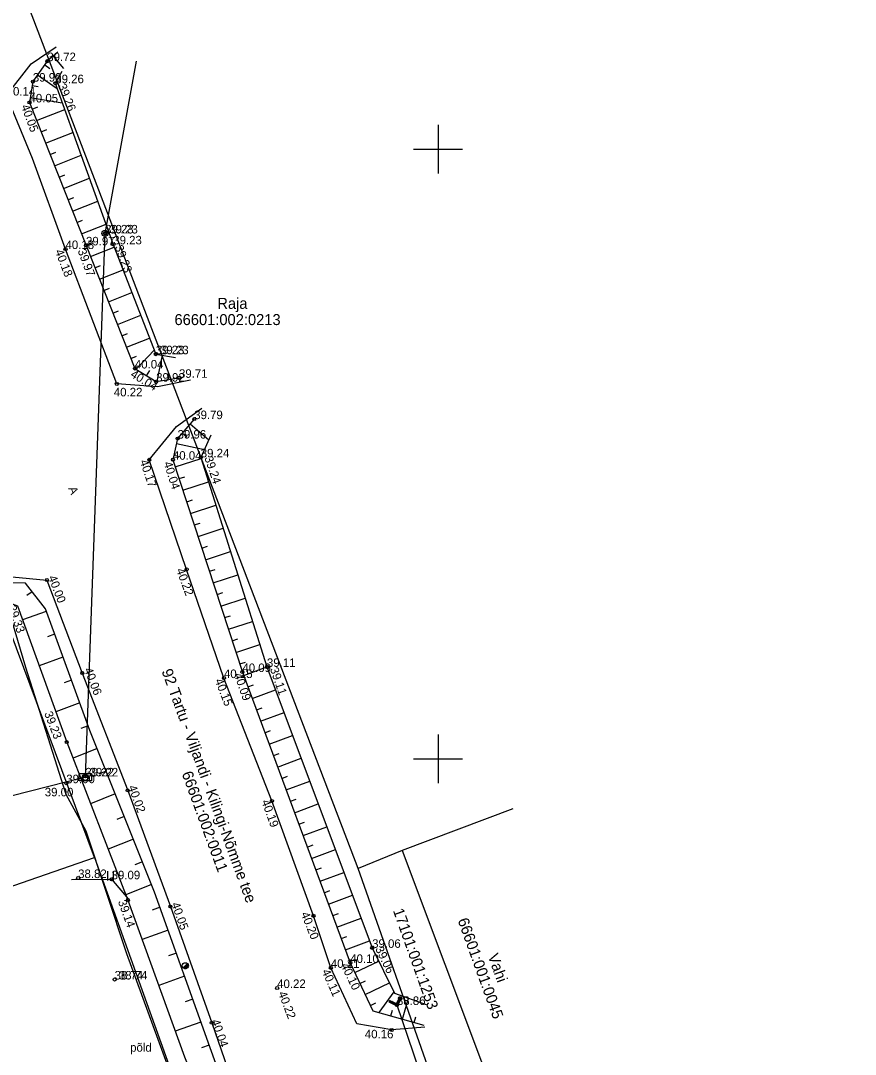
# Model space of a CAD drawing. Extents: x 627548 to 628052, y 6467984 to 6468802.
# Drawn here: x 627915.8 to 627984.2, y 6468175.8 to 6468260.5 of the extents above; entities that cross this region are included whole.
import ezdxf

# ---------------------------------------------------------------- set-up
doc = ezdxf.new("R2010")
doc.units = 0
for name, color, linetype in [('HALJASTUS', 7, 'Continuous'), ('KORGUS-EH2000', 7, 'Continuous'), ('MOOTKORG-EH2000', 7, 'Continuous'), ('MOOTMPUNKT', 7, 'Continuous'), ('PIIR', 7, 'Continuous'), ('POST', 7, 'Continuous'), ('RELJEEF', 7, 'Continuous'), ('SIOHULIIN', 7, 'Continuous'), ('SIRAJATIS', 7, 'Continuous'), ('SITRASS', 7, 'Continuous'), ('TEE', 7, 'Continuous'), ('TRUUP', 7, 'Continuous'), ('VORK', 7, 'Continuous')]:
    doc.layers.add(name, color=color, linetype=linetype)

msp = doc.modelspace()

# ---------------------------------------------------------------- linework, layer by layer
at = {"layer": 'HALJASTUS'}
for p, q in [((627922.905, 6468190.795), (627922.905, 6468190.034)), ((627923.36, 6468190.795), (627923.36, 6468190.034))]:
    msp.add_line(p, q, dxfattribs=at)
msp.add_lwpolyline([(627919.959, 6468190.107), (627923.237, 6468190.127), (627924.591, 6468188.526)], dxfattribs=at)
at = {"layer": 'KORGUS-EH2000'}
for centre in [(627923.665, 6468230.752), (627926.319, 6468224.528), (627929.386, 6468215.545), (627917.929, 6468214.671), (627920.824, 6468207.045), (627919.56, 6468201.376), (627924.552, 6468197.415), (627936.38, 6468196.557), (627924.571, 6468188.424), (627928.058, 6468187.889), (627939.788, 6468187.132), (627931.441, 6468178.362), (627946.208, 6468177.769)]:
    msp.add_circle(centre, 0.125, dxfattribs=at)
at = {"layer": 'MOOTMPUNKT'}
for centre in [(627917.965, 6468257.226), (627916.782, 6468255.547), (627918.619, 6468255.417), (627916.503, 6468253.84), (627922.694, 6468243.094), (627919.456, 6468241.816), (627921.136, 6468242.114), (627923.372, 6468242.198), (627926.859, 6468233.189), (627925.144, 6468232.02), (627926.889, 6468230.941), (627928.761, 6468231.254), (627930.008, 6468227.867), (627928.647, 6468226.271), (627928.263, 6468224.537), (627930.544, 6468224.73), (627933.959, 6468207.125), (627935.971, 6468207.543), (627932.447, 6468206.631), (627919.518, 6468198.008), (627921.083, 6468198.563), (627920.492, 6468190.229), (627923.237, 6468190.127), (627944.596, 6468184.507), (627941.209, 6468182.861), (627942.802, 6468183.27), (627923.481, 6468181.909), (627936.808, 6468181.211), (627946.63, 6468179.82)]:
    msp.add_circle(centre, 0.125, dxfattribs=at)
at = {"layer": 'PIIR'}
for p, q in [((627943.46, 6468191.01), (627912.59, 6468271.79)), ((627921.83, 6468191.92), (627909.15, 6468225.92)), ((627956.132, 6468195.911), (627947.07, 6468192.48)), ((627912.649, 6468188.741), (627921.83, 6468191.92)), ((627921.83, 6468191.92), (627931.94, 6468163.68)), ((627947.07, 6468192.48), (627943.46, 6468191.01)), ((627947.07, 6468192.48), (627962.62, 6468151.07)), ((627957.93, 6468149.94), (627943.46, 6468191.01))]:
    msp.add_line(p, q, dxfattribs=at)
at = {"layer": 'POST'}
msp.add_line((627929.101, 6468182.861), (627929.455, 6468183.214), dxfattribs=at)
for centre in [(627922.694, 6468243.094), (627921.089, 6468198.49), (627929.278, 6468183.037)]:
    msp.add_circle(centre, 0.25, dxfattribs=at)
for radius, start, end in [(0.225, 224.85406, 45.03563), (0.2, 224.84272, 45.04698), (0.175, 224.82813, 45.06157), (0.15, 224.80867, 45.08103), (0.125, 224.78144, 45.10826), (0.1, 224.74058, 45.14911), (0.075, 224.67249, 45.2172), (0.05, 224.53632, 45.35338), (0.025, 224.12776, 45.76193)]:
    msp.add_arc((627929.278, 6468183.037), radius, start, end, dxfattribs=at)
at = {"layer": 'RELJEEF'}
for p, q in [((627918.441, 6468257.631), (627919.299, 6468256.621)), ((627917.749, 6468256.92), (627918.158, 6468256.632)), ((627917.173, 6468256.102), (627918.78, 6468254.97)), ((627916.73, 6468255.23), (627917.224, 6468255.15)), ((627916.569, 6468254.244), (627919.195, 6468253.814)), ((627916.72, 6468253.29), (627917.185, 6468253.474)), ((627917.088, 6468252.36), (627919.391, 6468253.27)), ((627917.455, 6468251.43), (627917.92, 6468251.614)), ((627917.823, 6468250.5), (627920.068, 6468251.387)), ((627918.19, 6468249.57), (627918.655, 6468249.754)), ((627918.558, 6468248.64), (627920.745, 6468249.504)), ((627918.925, 6468247.71), (627919.39, 6468247.894)), ((627919.292, 6468246.78), (627921.422, 6468247.621)), ((627919.66, 6468245.85), (627920.125, 6468246.034)), ((627920.027, 6468244.92), (627922.099, 6468245.738)), ((627920.395, 6468243.99), (627920.86, 6468244.174)), ((627920.762, 6468243.06), (627922.776, 6468243.855)), ((627921.13, 6468242.13), (627921.595, 6468242.313)), ((627921.499, 6468241.2), (627923.457, 6468241.978)), ((627921.868, 6468240.271), (627922.333, 6468240.455)), ((627922.237, 6468239.342), (627924.179, 6468240.113)), ((627922.606, 6468238.412), (627923.071, 6468238.597)), ((627922.975, 6468237.483), (627924.901, 6468238.247)), ((627923.344, 6468236.553), (627923.809, 6468236.738)), ((627923.713, 6468235.624), (627925.623, 6468236.382)), ((627924.082, 6468234.694), (627924.547, 6468234.879)), ((627924.451, 6468233.765), (627926.345, 6468234.517)), ((627925.248, 6468231.956), (627926.728, 6468233.527)), ((627924.82, 6468232.836), (627925.285, 6468233.02)), ((627926.959, 6468230.953), (627927.396, 6468233.104)), ((627926.099, 6468231.43), (627926.362, 6468231.855)), ((627927.945, 6468231.118), (627927.863, 6468231.611)), ((627929.035, 6468226.726), (627929.415, 6468226.401)), ((627929.684, 6468227.487), (627931.214, 6468226.181)), ((627928.56, 6468225.878), (627930.841, 6468225.373)), ((627928.344, 6468224.902), (627928.832, 6468224.794)), ((627928.458, 6468223.942), (627930.574, 6468224.634)), ((627928.769, 6468222.991), (627929.244, 6468223.147)), ((627929.08, 6468222.041), (627931.177, 6468222.727)), ((627929.391, 6468221.09), (627929.866, 6468221.246)), ((627929.701, 6468220.14), (627931.779, 6468220.819)), ((627930.012, 6468219.189), (627930.488, 6468219.345)), ((627930.323, 6468218.239), (627932.381, 6468218.912)), ((627930.634, 6468217.289), (627931.109, 6468217.444)), ((627930.945, 6468216.338), (627932.983, 6468217.005)), ((627931.256, 6468215.388), (627931.731, 6468215.543)), ((627931.567, 6468214.437), (627933.586, 6468215.098)), ((627916.711, 6468213.714), (627916.292, 6468213.39)), ((627931.878, 6468213.487), (627932.353, 6468213.642)), ((627932.189, 6468212.536), (627934.188, 6468213.19)), ((627917.878, 6468212.102), (627915.942, 6468211.395)), ((627932.5, 6468211.586), (627932.975, 6468211.741)), ((627932.811, 6468210.635), (627934.79, 6468211.283)), ((627918.564, 6468210.223), (627917.981, 6468210.01)), ((627933.122, 6468209.685), (627933.597, 6468209.84)), ((627933.432, 6468208.735), (627935.392, 6468209.376)), ((627919.25, 6468208.344), (627917.3, 6468207.632)), ((627933.743, 6468207.784), (627934.219, 6468207.94)), ((627934.066, 6468206.838), (627935.971, 6468207.544)), ((627919.936, 6468206.466), (627919.349, 6468206.251)), ((627934.413, 6468205.9), (627934.882, 6468206.074)), ((627934.761, 6468204.962), (627936.672, 6468205.671)), ((627920.622, 6468204.587), (627918.659, 6468203.87)), ((627935.108, 6468204.025), (627935.577, 6468204.198)), ((627935.456, 6468203.087), (627937.373, 6468203.798)), ((627921.308, 6468202.708), (627920.717, 6468202.493)), ((627935.803, 6468202.149), (627936.272, 6468202.323)), ((627936.151, 6468201.212), (627938.075, 6468201.925)), ((627922.041, 6468200.848), (627920.07, 6468200.057)), ((627936.499, 6468200.274), (627936.967, 6468200.448)), ((627936.846, 6468199.336), (627938.776, 6468200.052)), ((627922.785, 6468198.991), (627922.187, 6468198.751)), ((627937.194, 6468198.399), (627937.663, 6468198.573)), ((627937.541, 6468197.461), (627939.477, 6468198.179)), ((627923.53, 6468197.135), (627921.514, 6468196.326)), ((627937.889, 6468196.523), (627938.358, 6468196.697)), ((627938.237, 6468195.586), (627940.178, 6468196.306)), ((627924.274, 6468195.279), (627923.662, 6468195.033)), ((627938.584, 6468194.648), (627939.053, 6468194.822)), ((627938.932, 6468193.711), (627940.88, 6468194.433)), ((627925.019, 6468193.422), (627922.957, 6468192.596)), ((627939.279, 6468192.773), (627939.748, 6468192.947)), ((627939.627, 6468191.835), (627941.581, 6468192.56)), ((627925.763, 6468191.566), (627925.138, 6468191.315)), ((627939.974, 6468190.898), (627940.443, 6468191.071)), ((627940.322, 6468189.96), (627942.282, 6468190.687)), ((627926.508, 6468189.71), (627924.4, 6468188.865)), ((627940.67, 6468189.022), (627941.138, 6468189.196)), ((627941.017, 6468188.085), (627942.984, 6468188.814)), ((627927.204, 6468187.835), (627926.56, 6468187.606)), ((627941.365, 6468187.147), (627941.834, 6468187.321)), ((627941.712, 6468186.209), (627943.685, 6468186.941)), ((627927.875, 6468185.951), (627925.738, 6468185.19)), ((627942.06, 6468185.272), (627942.529, 6468185.445)), ((627942.408, 6468184.334), (627944.386, 6468185.068)), ((627928.546, 6468184.067), (627927.907, 6468183.84)), ((627942.755, 6468183.396), (627943.224, 6468183.57)), ((627943.172, 6468182.488), (627945.135, 6468183.418)), ((627929.216, 6468182.183), (627927.095, 6468181.428)), ((627943.6, 6468181.584), (627944.052, 6468181.798)), ((627944.029, 6468180.681), (627946.023, 6468181.625)), ((627929.887, 6468180.299), (627929.253, 6468180.073)), ((627945.161, 6468179.2), (627946.389, 6468180.885)), ((627947.085, 6468178.652), (627947.578, 6468180.383)), ((627944.457, 6468179.777), (627944.909, 6468179.991)), ((627946.123, 6468178.926), (627946.26, 6468179.407)), ((627930.558, 6468178.415), (627928.453, 6468177.665)), ((627948.047, 6468178.378), (627948.184, 6468178.859)), ((627931.229, 6468176.531), (627930.6, 6468176.307))]:
    msp.add_line(p, q, dxfattribs=at)
for points in [[(627918.822, 6468257.955), (627917.965, 6468257.226), (627916.782, 6468255.547), (627916.503, 6468253.84), (627921.136, 6468242.114), (627925.144, 6468232.02), (627926.889, 6468230.941), (627928.761, 6468231.254)], [(627919.162, 6468256.378), (627918.619, 6468255.417), (627923.372, 6468242.198), (627926.859, 6468233.189), (627928.484, 6468232.931)], [(627930.008, 6468227.867), (627928.647, 6468226.271), (627928.263, 6468224.537), (627933.959, 6468207.125), (627942.802, 6468183.27), (627944.663, 6468179.342), (627948.843, 6468178.151)], [(627931.38, 6468226.54), (627930.544, 6468224.73), (627935.971, 6468207.543), (627944.596, 6468184.507), (627946.439, 6468180.784), (627949.028, 6468179.871)], [(627978.291, 6468008.882), (627983.457, 6468013.678), (627984.21, 6468021.024), (627979.575, 6468037.02), (627973.979, 6468054.36), (627968.222, 6468070.605), (627961.466, 6468089.433), (627957.405, 6468099.776), (627954.697, 6468099.952), (627954.601, 6468100.77), (627956.677, 6468103.285), (627952.114, 6468117.091), (627946.482, 6468133.262), (627941.383, 6468147.782), (627936.221, 6468162.714), (627931.414, 6468176.011), (627926.765, 6468189.068), (627921.448, 6468202.325), (627917.805, 6468212.302), (627916.173, 6468214.408), (627912.962, 6468214.481), (627910.459, 6468214.182)], [(627910.966, 6468212.647), (627913.157, 6468213.418), (627915.522, 6468212.557), (627919.56, 6468201.376), (627924.571, 6468188.424), (627929.207, 6468175.576), (627934.909, 6468161.365), (627939.161, 6468147.561), (627944.576, 6468131.872), (627949.813, 6468116.897), (627954.804, 6468102.831), (627953.147, 6468101.408), (627953.982, 6468098.417), (627956.488, 6468098.118), (627959.583, 6468088.974), (627966.658, 6468069.004), (627971.68, 6468054.444), (627977.14, 6468035.885), (627981.189, 6468020.389), (627981.639, 6468013.545), (627978.211, 6468009.476)]]:
    msp.add_lwpolyline(points, dxfattribs=at)
at = {"layer": 'SIOHULIIN'}
msp.add_lwpolyline([(627921.089, 6468198.49), (627922.694, 6468243.094), (627925.287, 6468257.213)], dxfattribs=at)
at = {"layer": 'SIRAJATIS'}
msp.add_lwpolyline([(627920.589, 6468198.79), (627921.589, 6468198.79), (627921.589, 6468198.19), (627920.589, 6468198.19)], close=True, dxfattribs=at)
for centre, radius in [((627920.889, 6468198.49), 0.0304), ((627920.889, 6468198.49), 0.029), ((627920.889, 6468198.49), 0.0277), ((627920.889, 6468198.49), 0.0263), ((627920.889, 6468198.49), 0.0249), ((627920.889, 6468198.49), 0.0236), ((627920.889, 6468198.49), 0.0222), ((627920.889, 6468198.49), 0.0209), ((627920.889, 6468198.49), 0.0195), ((627920.889, 6468198.49), 0.0181), ((627920.889, 6468198.49), 0.0168), ((627920.889, 6468198.49), 0.0154), ((627920.889, 6468198.49), 0.014), ((627920.889, 6468198.49), 0.0127), ((627920.889, 6468198.49), 0.0113), ((627920.889, 6468198.49), 0.00996), ((627920.889, 6468198.49), 0.0086), ((627920.889, 6468198.49), 0.00724), ((627920.889, 6468198.49), 0.00587), ((627920.889, 6468198.49), 0.00451), ((627920.889, 6468198.49), 0.00315), ((627920.889, 6468198.49), 0.00179), ((627920.889, 6468198.49), 0.000426), ((627921.289, 6468198.49), 0.0304), ((627921.289, 6468198.49), 0.029), ((627921.289, 6468198.49), 0.0277), ((627921.289, 6468198.49), 0.0263), ((627921.289, 6468198.49), 0.0249), ((627921.289, 6468198.49), 0.0236), ((627921.289, 6468198.49), 0.0222), ((627921.289, 6468198.49), 0.0209), ((627921.289, 6468198.49), 0.0195), ((627921.289, 6468198.49), 0.0181), ((627921.289, 6468198.49), 0.0168), ((627921.289, 6468198.49), 0.0154), ((627921.289, 6468198.49), 0.014), ((627921.289, 6468198.49), 0.0127), ((627921.289, 6468198.49), 0.0113), ((627921.289, 6468198.49), 0.00996), ((627921.289, 6468198.49), 0.0086), ((627921.289, 6468198.49), 0.00724), ((627921.289, 6468198.49), 0.00587), ((627921.289, 6468198.49), 0.00451), ((627921.289, 6468198.49), 0.00315), ((627921.289, 6468198.49), 0.00179), ((627921.289, 6468198.49), 0.000426)]:
    msp.add_circle(centre, radius, dxfattribs=at)
at = {"layer": 'SITRASS'}
for points in [[(627921.089, 6468198.49), (627913.451, 6468196.558), (627912.303, 6468197.515), (627910.277, 6468205.003), (627909.336, 6468214.504), (627909.049, 6468220.619), (627907.566, 6468227.896), (627902.598, 6468241.864), (627900.363, 6468247.033), (627898.686, 6468250.201), (627896.535, 6468253.505), (627893.107, 6468260.449), (627888.841, 6468271.867)], [(627947.216, 6468119.583), (627940.944, 6468137.544), (627936.199, 6468151.108), (627931.361, 6468165.186), (627924.482, 6468184.013), (627921.137, 6468194.069), (627919.519, 6468197.087), (627916.208, 6468207.498), (627913.328, 6468217.079), (627911.258, 6468222.936), (627909.418, 6468228.846), (627904.458, 6468242.929), (627901.383, 6468250.765), (627898.374, 6468251.727), (627897.323, 6468252.46), (627895.041, 6468257.946), (627892.765, 6468263.751)]]:
    msp.add_lwpolyline(points, dxfattribs=at)
at = {"layer": 'TEE'}
for points in [[(627929.714, 6468231.069), (627927.009, 6468230.503), (627923.665, 6468230.752), (627919.456, 6468241.816), (627916.754, 6468249.254), (627914.631, 6468254.406), (627916.631, 6468257.007), (627918.692, 6468258.401)], [(627948.923, 6468177.988), (627946.208, 6468177.769), (627943.331, 6468178.271), (627941.209, 6468182.861), (627939.788, 6468187.132), (627936.38, 6468196.557), (627932.447, 6468206.631), (627929.386, 6468215.545), (627926.319, 6468224.528), (627928.552, 6468227.259), (627930.624, 6468228.766)], [(627910.11, 6468214.994), (627913.055, 6468215.115), (627917.929, 6468214.671), (627920.824, 6468207.045), (627924.552, 6468197.415), (627928.058, 6468187.889), (627931.441, 6468178.362), (627934.781, 6468168.694), (627938.378, 6468158.823), (627941.796, 6468149.304), (627945.301, 6468139.654), (627948.73, 6468130.073), (627952.157, 6468120.49)]]:
    msp.add_lwpolyline(points, dxfattribs=at)
at = {"layer": 'TRUUP'}
for p, q in [((627946.024, 6468180.192), (627945.962, 6468180.064)), ((627945.962, 6468180.064), (627946.663, 6468179.725)), ((627945.975, 6468180.09), (627946.015, 6468180.038)), ((627945.987, 6468180.115), (627946.065, 6468180.014)), ((627945.993, 6468180.128), (627946.63, 6468179.82)), ((627946, 6468180.141), (627946.115, 6468179.99)), ((627946.012, 6468180.166), (627946.165, 6468179.966)), ((627946.024, 6468180.192), (627946.597, 6468179.915)), ((627946.024, 6468180.191), (627946.215, 6468179.942)), ((627946.073, 6468180.169), (627946.265, 6468179.917)), ((627946.123, 6468180.144), (627946.315, 6468179.893)), ((627946.173, 6468180.12), (627946.365, 6468179.869)), ((627946.223, 6468180.096), (627946.415, 6468179.845)), ((627946.273, 6468180.072), (627946.465, 6468179.821)), ((627946.323, 6468180.048), (627946.515, 6468179.797)), ((627946.597, 6468179.915), (627946.874, 6468180.488)), ((627946.63, 6468179.82), (627946.938, 6468180.457)), ((627946.663, 6468179.725), (627947.002, 6468180.426)), ((627946.664, 6468180.054), (627946.761, 6468179.928)), ((627946.676, 6468180.079), (627946.773, 6468179.953)), ((627946.689, 6468180.105), (627946.785, 6468179.978)), ((627946.701, 6468180.13), (627946.798, 6468180.003)), ((627946.713, 6468180.155), (627946.81, 6468180.028)), ((627946.725, 6468180.18), (627946.822, 6468180.054)), ((627946.737, 6468180.205), (627946.834, 6468180.079)), ((627946.749, 6468180.231), (627946.846, 6468180.104)), ((627946.762, 6468180.256), (627946.859, 6468180.129)), ((627946.774, 6468180.281), (627946.871, 6468180.154)), ((627946.786, 6468180.306), (627946.883, 6468180.18)), ((627946.798, 6468180.331), (627946.895, 6468180.205)), ((627946.81, 6468180.357), (627946.907, 6468180.23)), ((627946.823, 6468180.382), (627946.92, 6468180.255)), ((627946.835, 6468180.407), (627946.932, 6468180.28)), ((627946.847, 6468180.432), (627946.944, 6468180.306)), ((627946.859, 6468180.457), (627946.956, 6468180.331)), ((627946.871, 6468180.483), (627946.968, 6468180.356)), ((627946.874, 6468180.488), (627947.002, 6468180.426)), ((627946.914, 6468180.468), (627946.98, 6468180.381)), ((627946.964, 6468180.444), (627946.993, 6468180.406)), ((627946.373, 6468180.023), (627946.565, 6468179.772)), ((627946.423, 6468179.999), (627946.615, 6468179.748)), ((627946.473, 6468179.975), (627946.664, 6468179.726)), ((627946.523, 6468179.951), (627946.676, 6468179.751)), ((627946.573, 6468179.927), (627946.688, 6468179.776)), ((627946.603, 6468179.928), (627946.7, 6468179.802)), ((627946.615, 6468179.953), (627946.712, 6468179.827)), ((627946.628, 6468179.979), (627946.725, 6468179.852)), ((627946.64, 6468180.004), (627946.737, 6468179.877)), ((627946.652, 6468180.029), (627946.749, 6468179.902))]:
    msp.add_line(p, q, dxfattribs=at)
msp.add_lwpolyline([(627946.63, 6468179.82), (627949.339, 6468171.88)], dxfattribs=at)
at = {"layer": 'VORK'}
for p, q in [((627950, 6468252), (627950, 6468248)), ((627948, 6468250), (627952, 6468250)), ((627950, 6468202), (627950, 6468198)), ((627948, 6468200), (627952, 6468200))]:
    msp.add_line(p, q, dxfattribs=at)

# ---------------------------------------------------------------- texts
at = {"layer": 'HALJASTUS'}
msp.add_text('põld', height=0.7, dxfattribs=at).set_placement((627924.753, 6468175.986))
at = {"layer": 'KORGUS-EH2000'}
for s, rotation, p in [('39.26', 291.82215, (627918.824, 6468255.216)), ('40.05', 290.21608, (627915.802, 6468253.53)), ('39.23', 290.42778, (627923.483, 6468241.993)), ('40.18', 291.07094, (627918.581, 6468241.64)), ('39.97', 290.50712, (627920.437, 6468241.679)), ('40.04', 328.51307, (627924.722, 6468231.37)), (' 40.17', 288.85107, (627925.449, 6468224.661)), ('40.04', 287.67034, (627927.491, 6468224.269)), ('39.24', 288.6954, (627930.833, 6468224.705)), (' 40.00', 290.78788, (627917.934, 6468215.147)), (' 40.22', 290.18379, (627928.429, 6468215.745)), (' 39.33', 289.8571, (627914.625, 6468212.704)), (' 40.06', 291.1626, (627920.876, 6468207.577)), ('39.11', 288.99215, (627936.209, 6468207.381)), ('40.15', 291.2054, (627931.686, 6468206.44)), ('40.09', 289.3877, (627933.26, 6468206.919)), (' 39.23', 291.15096, (627917.6, 6468203.984)), (' 40.02', 290.2059, (627924.494, 6468197.949)), (' 40.19', 289.87956, (627935.421, 6468196.764)), (' 39.14', 289.84119, (627923.653, 6468188.544)), (' 40.05', 289.54975, (627928.035, 6468188.351)), (' 40.20', 291.79361, (627938.646, 6468187.537)), ('39.06', 295.78143, (627944.827, 6468184.435)), ('40.11', 293.81343, (627940.453, 6468182.583)), ('40.10', 295.56895, (627942.009, 6468183.075)), ('40.22', 291.0053, (627936.881, 6468180.792)), (' 40.04', 289.05847, (627931.323, 6468178.753))]:
    msp.add_text(s, height=0.7, rotation=rotation, dxfattribs=at).set_placement(p)
for s, p in [('39.23', (627923.044, 6468243.094)), ('39.23', (627927.209, 6468233.189)), (' 40.22', (627923.159, 6468229.734)), ('39.22', (627921.433, 6468198.563)), ('39.00', (627917.757, 6468196.93)), ('38.74', (627923.831, 6468181.909)), (' 40.16', (627943.737, 6468177.085))]:
    msp.add_text(s, height=0.7, dxfattribs=at).set_placement(p)
at = {"layer": 'MOOTKORG-EH2000'}
for s, p in [('39.72', (627917.965, 6468257.226)), ('39.93', (627916.782, 6468255.547)), ('39.26', (627918.619, 6468255.417)), ('40.14', (627914.631, 6468254.406)), ('40.05', (627916.503, 6468253.84)), ('39.23', (627922.694, 6468243.094)), ('39.97', (627921.136, 6468242.114)), ('39.23', (627923.372, 6468242.198)), ('40.18', (627919.456, 6468241.816)), ('39.23', (627926.859, 6468233.189)), ('40.04', (627925.144, 6468232.02)), ('39.71', (627928.761, 6468231.254)), ('39.92', (627926.889, 6468230.941)), ('39.79', (627930.008, 6468227.867)), ('39.96', (627928.647, 6468226.271)), ('40.04', (627928.263, 6468224.537)), ('39.24', (627930.544, 6468224.73)), ('39.11', (627935.971, 6468207.543)), ('40.15', (627932.447, 6468206.631)), ('40.09', (627933.959, 6468207.125)), ('39.00', (627919.518, 6468198.008)), ('39.22', (627921.083, 6468198.563)), ('38.82', (627920.492, 6468190.229)), ('39.09', (627923.237, 6468190.127)), ('39.06', (627944.596, 6468184.507)), ('40.11', (627941.209, 6468182.861)), ('40.10', (627942.802, 6468183.27)), ('38.74', (627923.481, 6468181.909)), ('40.22', (627936.808, 6468181.211)), ('38.86', (627946.63, 6468179.82))]:
    msp.add_text(s, height=0.7, dxfattribs=at).set_placement(p)
at = {"layer": 'PIIR'}
for s, p in [('Raja', (627931.901, 6468236.911)), ('66601:002:0213', (627928.39, 6468235.58))]:
    msp.add_text(s, height=0.9, dxfattribs=at).set_placement(p)
for s, rotation, p in [('92 Tartu - Viljandi - Kilingi-Nõmme tee', 290.07936, (627927.321, 6468207.197)), ('66601:002:0011', 290.07936, (627928.972, 6468198.803)), ('17101:001:1253', 289.56788, (627946.29, 6468187.568)), ('66601:001:0045', 289.80362, (627951.596, 6468186.773)), ('Vahi', 289.80362, (627954.064, 6468183.848))]:
    msp.add_text(s, height=0.9, rotation=rotation, dxfattribs=at).set_placement(p)
at = {"layer": 'TEE'}
msp.add_text('A', height=0.7, rotation=292.11557, dxfattribs=at).set_placement((627919.671, 6468222.18))

doc.saveas('drawing.dxf')
